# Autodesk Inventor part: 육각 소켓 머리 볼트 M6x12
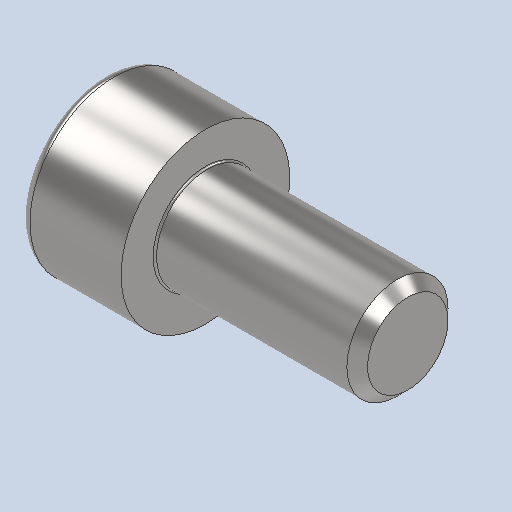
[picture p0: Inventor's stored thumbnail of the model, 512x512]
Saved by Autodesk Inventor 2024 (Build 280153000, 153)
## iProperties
Created: 2024-08
Part Number: 육각 소켓 머리 볼트 M6x12
Material: 강철, 연강
Description: 6각머리 태핑 나사
Document SubType Name: Modeling
Designer: user
Density: 7.85 g/cm^3
Appearance: 기본값
Author: jhkim
Sending System: Autodesk Inventor 2025
Preprocessor: ST-DEVELOPER v20
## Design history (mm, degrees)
feature "Solid1"
node "솔리드1"
